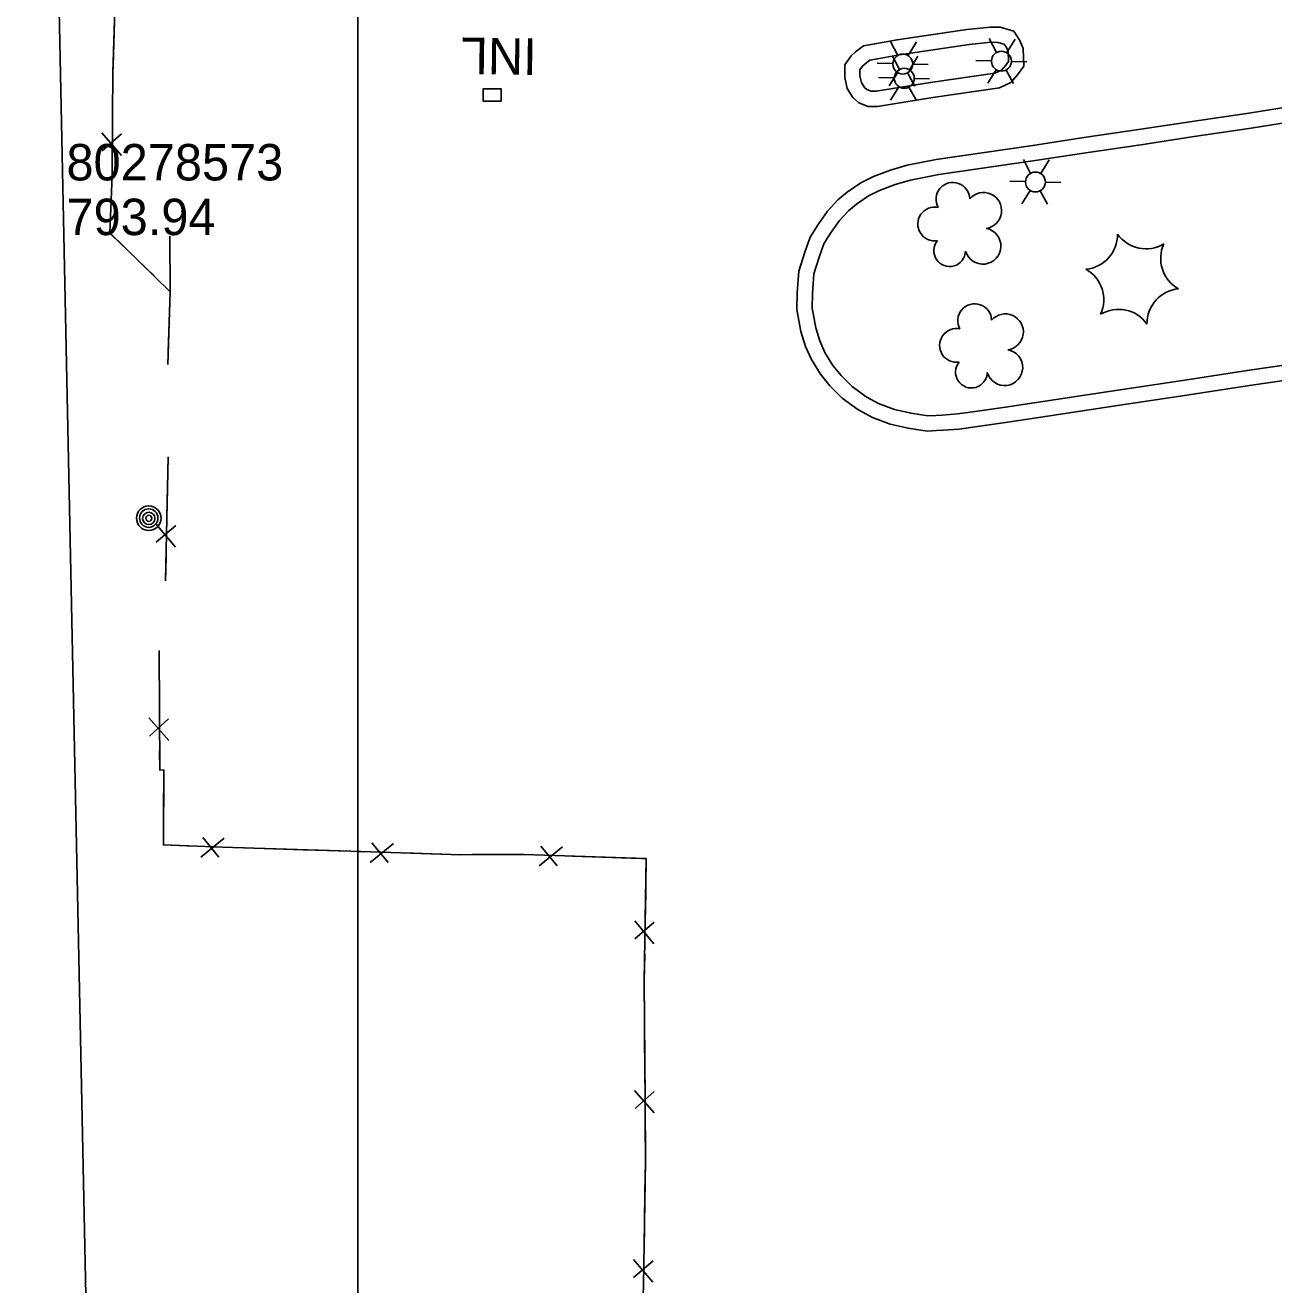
# Model space of a CAD drawing. Extents: x 591954 to 597000, y 198576 to 213500.
# Drawn here: x 593445.3 to 593650.8, y 210505.2 to 210712.6 of the extents above; entities that cross this region are included whole.
import ezdxf

# ---------------------------------------------------------------- set-up
doc = ezdxf.new("R2010")
doc.units = 0
for name, color, linetype in [('Level 10', 7, 'Continuous'), ('Level 14', 7, 'Continuous'), ('Level 15', 7, 'Continuous'), ('Level 17', 7, 'Continuous'), ('Level 18', 7, 'Continuous'), ('Level 4', 7, 'Continuous'), ('Level 6', 7, 'Continuous')]:
    doc.layers.add(name, color=color, linetype=linetype)

msp = doc.modelspace()

# ---------------------------------------------------------------- linework, layer by layer
at = {"layer": 'Level 10'}
msp.add_line((593500, 210000), (593500, 211500), dxfattribs=at)
at = {"layer": 'Level 14'}
for p, q in [((593588.95, 210707.6), (593587.75, 210709.9)), ((593605.19, 210708.07), (593603.99, 210710.37)), ((593606.89, 210708.06), (593608.26, 210710.29)), ((593590.65, 210707.59), (593592.02, 210709.82)), ((593588.11, 210706.24), (593585.51, 210706.31)), ((593589.19, 210705.26), (593587.99, 210707.56)), ((593590.89, 210705.25), (593592.25, 210707.48)), ((593591.39, 210706.15), (593593.91, 210706.08)), ((593604.35, 210706.7), (593601.75, 210706.77)), ((593607.63, 210706.61), (593610.15, 210706.54)), ((593588.35, 210703.9), (593585.75, 210703.97)), ((593588.87, 210704.75), (593587.51, 210702.56)), ((593590.51, 210704.7), (593591.75, 210702.52)), ((593591.63, 210703.81), (593594.15, 210703.74)), ((593605.11, 210705.21), (593603.75, 210703.02)), ((593606.75, 210705.17), (593607.99, 210702.99)), ((593589.11, 210702.41), (593587.75, 210700.22)), ((593590.74, 210702.36), (593591.99, 210700.18)), ((593610.8, 210688.18), (593609.6, 210690.48)), ((593612.5, 210688.17), (593613.86, 210690.4)), ((593609.96, 210686.82), (593607.36, 210686.89)), ((593610.72, 210685.33), (593609.35, 210683.14)), ((593612.35, 210685.28), (593613.6, 210683.1)), ((593613.23, 210686.73), (593615.76, 210686.66))]:
    msp.add_line(p, q, dxfattribs=at)
for centre, radius in [((593589.75, 210706.17), 1.64), ((593605.99, 210706.64), 1.64), ((593589.99, 210703.83), 1.64), ((593611.59, 210686.75), 1.64), ((593465.6, 210631.41), 2.02), ((593465.6, 210631.42), 1.52), ((593465.6, 210631.38), 1.01), ((593465.61, 210631.39), 0.502)]:
    msp.add_circle(centre, radius, dxfattribs=at)
at = {"layer": 'Level 15'}
for p, q in [((593457.87, 210694.84), (593461.09, 210691.11)), ((593461.11, 210694.66), (593457.93, 210691.88)), ((593466.83, 210630.43), (593469.99, 210626.64)), ((593470.07, 210630.19), (593466.83, 210627.46)), ((593465.63, 210598.52), (593468.88, 210594.81)), ((593468.87, 210598.36), (593465.71, 210595.55)), ((593474.2, 210575.63), (593478.04, 210578.72)), ((593474.49, 210578.86), (593477.16, 210575.58)), ((593502.06, 210574.74), (593505.87, 210577.86)), ((593502.33, 210577.97), (593505.02, 210574.71)), ((593529.9, 210574.2), (593533.72, 210577.32)), ((593530.18, 210577.43), (593532.87, 210574.17)), ((593545.61, 210565.1), (593548.78, 210561.33)), ((593548.84, 210564.88), (593545.62, 210562.14)), ((593545.57, 210537.21), (593548.83, 210533.51)), ((593548.81, 210537.05), (593545.66, 210534.24)), ((593545.39, 210509.38), (593548.58, 210505.62)), ((593548.63, 210509.17), (593545.42, 210506.42))]:
    msp.add_line(p, q, dxfattribs=at)
for points in [[(593460.6, 210761.66), (593460.58, 210752.05), (593460.59, 210746.18), (593460.29, 210731.8), (593460.07, 210716.87), (593459.7, 210704.79), (593459.62, 210697.64), (593459.58, 210687.85), (593459.18, 210678.38), (593469.12, 210668.7)], [(593460.08, 210717.27), (593460.07, 210716.87), (593459.74, 210705.95)], [(593459.74, 210705.95), (593459.7, 210704.79), (593459.62, 210697.64), (593459.61, 210696)], [(593523.65, 210700.07), (593523.65, 210702.07), (593520.65, 210702.07), (593520.65, 210700.07), (593523.65, 210700.07)], [(593459.59, 210689.42), (593459.58, 210687.85), (593459.18, 210678.38), (593459.38, 210678.19)], [(593459.38, 210678.19), (593466.52, 210671.24)], [(593469.12, 210668.7), (593469.09, 210677.85)], [(593469.12, 210668.7), (593469.09, 210677.85)], [(593469.12, 210668.7), (593468.76, 210656.71)], [(593469.12, 210668.7), (593468.82, 210658.75)], [(593468.81, 210641.51), (593468.37, 210621.08)], [(593468.81, 210641.51), (593468.59, 210631.55)], [(593468.45, 210624.97), (593468.37, 210621.08)], [(593467.32, 210609.64), (593467.4, 210589.94), (593468.07, 210589.96), (593468, 210577.61), (593477.67, 210577.24), (593498.89, 210576.58), (593516.98, 210576.01), (593527.39, 210576.02), (593547.52, 210575.36), (593547.18, 210555.23), (593547.32, 210535.75), (593547.37, 210525.53), (593547.07, 210505.21), (593546.48, 210484.9), (593546.74, 210464.96), (593546.49, 210445.54), (593546.5, 210434.03)], [(593467.32, 210609.64), (593467.36, 210599.68)], [(593467.39, 210593.1), (593467.4, 210589.94), (593468.07, 210589.96), (593468.03, 210582.46)], [(593468.03, 210582.46), (593468, 210577.61), (593473.1, 210577.41)], [(593479.68, 210577.17), (593491, 210576.82)], [(593491, 210576.82), (593498.89, 210576.58), (593500.95, 210576.51)], [(593507.53, 210576.31), (593516.98, 210576.01), (593518.84, 210576.02)], [(593518.84, 210576.02), (593527.39, 210576.02), (593528.8, 210575.98)], [(593535.38, 210575.76), (593546.69, 210575.39)], [(593546.69, 210575.39), (593547.52, 210575.36), (593547.36, 210566.23)], [(593547.25, 210559.65), (593547.18, 210555.23), (593547.23, 210548.33)], [(593547.23, 210548.33), (593547.3, 210538.38)], [(593547.34, 210531.79), (593547.37, 210525.53), (593547.3, 210520.47)], [(593547.3, 210520.47), (593547.15, 210510.52)]]:
    msp.add_lwpolyline(points, dxfattribs=at)
at = {"layer": 'Level 17'}
for points in [[(593600.32, 210711.88), (593588.8, 210710.18), (593585.12, 210709.5), (593583.3, 210709.15), (593581.99, 210708.17), (593581.24, 210707.51), (593580.2, 210706.04), (593580.19, 210703.98), (593580.59, 210702.17), (593581.53, 210700.65), (593582.53, 210699.81), (593584.06, 210699.16), (593585.6, 210699.21), (593594.7, 210700.64), (593605.67, 210702.24), (593607.52, 210703.13), (593608.65, 210704.4), (593609.7, 210705.82), (593609.55, 210708.75), (593609.02, 210710.07), (593608.02, 210711.57), (593605.8, 210712.24), (593604.16, 210712.26), (593600.32, 210711.88)], [(593600.69, 210709.4), (593589.21, 210707.71), (593585.58, 210707.04), (593584.33, 210706.8), (593583.56, 210706.22), (593583.11, 210705.83), (593582.7, 210705.24), (593582.69, 210704.24), (593582.94, 210703.12), (593583.45, 210702.3), (593583.85, 210701.96), (593584.53, 210701.68), (593585.37, 210701.71), (593594.33, 210703.11), (593604.93, 210704.66), (593605.98, 210705.17), (593606.7, 210705.98), (593607.16, 210706.59), (593607.08, 210708.21), (593606.8, 210708.9), (593606.44, 210709.43), (593605.41, 210709.74), (593604.27, 210709.76), (593600.69, 210709.4)], [(593657.03, 210654.75), (593646.82, 210653.24), (593636.54, 210651.66), (593625.5, 210650.03), (593615.37, 210648.49), (593607.02, 210647.23), (593601.64, 210646.44), (593599.02, 210646.09), (593596.39, 210645.88), (593595.3, 210645.84), (593593.77, 210645.76), (593590.65, 210646.22), (593587.67, 210646.9), (593584.74, 210647.99), (593582.36, 210649.28), (593579.76, 210651.18), (593577.72, 210653.21), (593576.18, 210655.11), (593574.71, 210657.51), (593573.73, 210659.7), (593572.97, 210662.17), (593572.32, 210665.79), (593572.36, 210668.52), (593572.65, 210672.1), (593573.6, 210675.18), (593574.48, 210677.67), (593575.79, 210679.73), (593577.36, 210681.97), (593579.07, 210683.82), (593580.6, 210685.1), (593582.83, 210686.62), (593584.9, 210687.64), (593587.72, 210688.72), (593590.46, 210689.5), (593595.25, 210690.44), (593611.18, 210692.75), (593619.54, 210694.06), (593628.95, 210695.43), (593636.99, 210696.66), (593646.74, 210698.07), (593654.93, 210699.38)], [(593656.65, 210657.23), (593646.45, 210655.71), (593636.17, 210654.13), (593625.13, 210652.51), (593614.99, 210650.96), (593606.65, 210649.7), (593601.29, 210648.92), (593598.75, 210648.58), (593596.25, 210648.37), (593595.2, 210648.33), (593593.89, 210648.27), (593591.12, 210648.68), (593588.39, 210649.3), (593585.77, 210650.27), (593583.7, 210651.4), (593581.39, 210653.08), (593579.58, 210654.89), (593578.22, 210656.55), (593576.93, 210658.68), (593576.08, 210660.58), (593575.41, 210662.76), (593574.82, 210666), (593574.86, 210668.4), (593575.12, 210671.62), (593575.98, 210674.39), (593576.74, 210676.57), (593577.87, 210678.34), (593579.31, 210680.4), (593580.79, 210682.01), (593582.11, 210683.11), (593584.09, 210684.46), (593585.9, 210685.35), (593588.51, 210686.35), (593591.04, 210687.06), (593595.67, 210687.98), (593611.55, 210690.28), (593619.91, 210691.58), (593629.31, 210692.95), (593637.36, 210694.18), (593647.12, 210695.6), (593655.31, 210696.91)]]:
    msp.add_lwpolyline(points, dxfattribs=at)
at = {"layer": 'Level 18'}
for centre, radius, start, end in [((593598, 210683.91), 2.78, 1.3946, 209.1675), ((593603.05, 210682.06), 2.97, 278.4237, 139.6575), ((593595, 210679.84), 2.78, 78.0716, 279.0826), ((593602.93, 210676.2), 2.97, 196.0745, 79.0477), ((593597.47, 210675.44), 2.61, 140.7797, 358.7123), ((593619.38, 210678.08), 5.72, 275.2113, 0.9762), ((593629.78, 210681.48), 5.72, 215.2113, 300.9762), ((593637.93, 210674.17), 5.72, 155.2113, 240.9762), ((593617.13, 210667.38), 5.72, 335.2113, 60.9762), ((593635.67, 210663.47), 5.72, 95.2113, 180.9762), ((593601.59, 210663.93), 2.78, 1.3946, 209.1675), ((593606.63, 210662.07), 2.97, 278.4237, 139.6575), ((593625.27, 210660.07), 5.72, 35.2113, 120.9762), ((593598.59, 210659.85), 2.78, 78.0716, 279.0826), ((593606.52, 210656.22), 2.97, 196.0745, 79.0477), ((593601.05, 210655.45), 2.61, 140.7797, 358.7123)]:
    msp.add_arc(centre, radius, start, end, dxfattribs=at)
at = {"layer": 'Level 4'}
msp.add_lwpolyline([(593564.94, 211321.29), (593445.25, 210984.77), (593456.88, 210424.19)], dxfattribs=at)

# ---------------------------------------------------------------- texts
at = {"layer": 'Level 15'}
msp.add_text('INL', height=6, rotation=179.1825, dxfattribs=at).set_placement((593529.52, 210710.37))
at = {"layer": 'Level 6'}
for s, p in [('80278573', (593452.05, 210687.01)), ('793.94', (593452.05, 210678.01))]:
    msp.add_text(s, height=6, dxfattribs=at).set_placement(p)

doc.saveas('drawing.dxf')
